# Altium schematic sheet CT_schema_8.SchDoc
size 281 x 153 mm
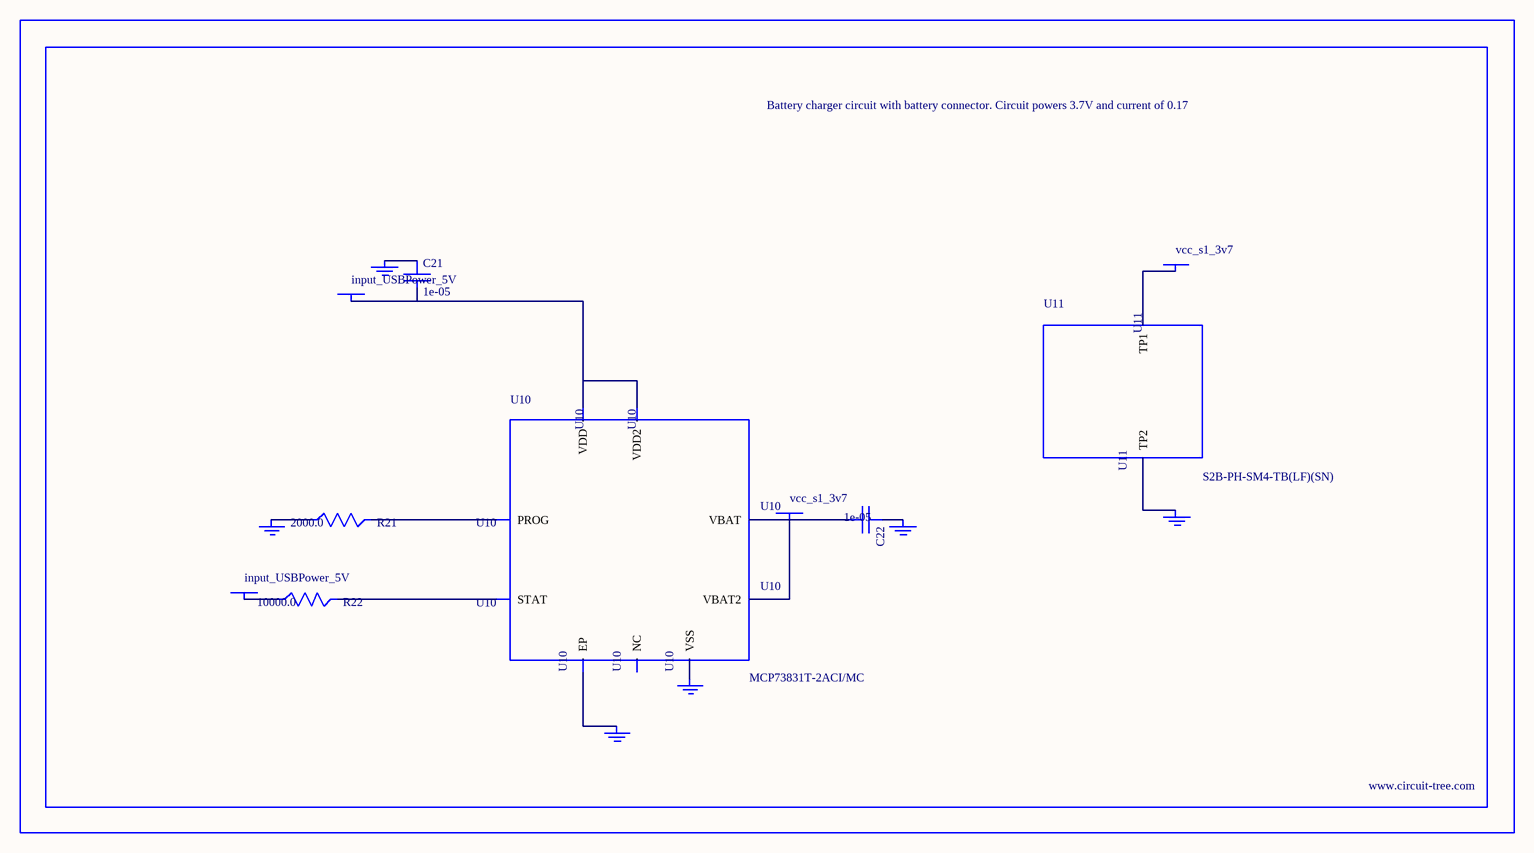
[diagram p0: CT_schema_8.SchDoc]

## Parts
BORDER7  (no value)
C21  1e-05  [C1206]
C22  1e-05  [C1206]
GND_INSTANCE_7_0  (no value)
GND_INSTANCE_7_1  (no value)
GND_INSTANCE_7_2  (no value)
GND_INSTANCE_7_3  (no value)
GND_INSTANCE_7_4  (no value)
GND_INSTANCE_7_5  (no value)
POWER_INSTANCE_7_0  input_USBPower_5V
POWER_INSTANCE_7_1  input_USBPower_5V
POWER_INSTANCE_7_2  vcc_s1_3v7
POWER_INSTANCE_7_3  vcc_s1_3v7
R21  2000.0  [R0603]
R22  10000.0  [R0603]
U10  MCP73831T-2ACI/MC  [DFN8_2X3MC]
U11  S2B-PH-SM4-TB(LF)(SN)  [JST-2-SMD]

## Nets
NetC21_1: C21.1 GND_INSTANCE_7_0.0(GND)
NetC21_2: C21.2 POWER_INSTANCE_7_0.0(PWR) U10.1(VDD) U10.2(VDD2)
NetC22_1: C22.1 GND_INSTANCE_7_1.0(GND)
NetC22_2: C22.2 POWER_INSTANCE_7_2.0(PWR) U10.3(VBAT) U10.4(VBAT2)
NetGND_INSTANCE_7_2_0: GND_INSTANCE_7_2.0(GND) R21.1
NetGND_INSTANCE_7_3_0: GND_INSTANCE_7_3.0(GND) U10.9(EP)
NetGND_INSTANCE_7_4_0: GND_INSTANCE_7_4.0(GND) U10.6(VSS)
NetGND_INSTANCE_7_5_0: GND_INSTANCE_7_5.0(GND) U11.2(TP2)
NetPOWER_INSTANCE_7_1_0: POWER_INSTANCE_7_1.0(PWR) R22.1
NetPOWER_INSTANCE_7_3_0: POWER_INSTANCE_7_3.0(PWR) U11.1(TP1)
NetR21_2: R21.2 U10.8(PROG)
NetR22_2: R22.2 U10.5(STAT)

Not connected (* = marked no-connect by the designer): U10 7(NC)

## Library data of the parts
BORDER7 = BORDER_PAGE7
C21 C22 = C1206C106K3RACTU
GND_INSTANCE_7_0-GND_INSTANCE_7_5 = GND
POWER_INSTANCE_7_0-POWER_INSTANCE_7_3 = PWR
R21 = RC0603JR-072KL
R22 = RC0603JR-0710KL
